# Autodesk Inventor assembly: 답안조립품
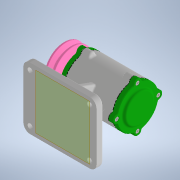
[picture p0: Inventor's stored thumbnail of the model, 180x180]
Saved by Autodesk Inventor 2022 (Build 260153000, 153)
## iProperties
Created: 2023-05
Part Number: 답안조립품
Document SubType Name: Assembly
Designer: Admin
Author: Admin
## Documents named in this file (12)
- C:\Users\Admin\Desktop\730508V1006\답안조립품.iam
- C:\Users\Admin\Desktop\730508V1006\본체.ipt
- C:\Users\Admin\Desktop\730508V1006\개스킷.ipt
- C:\Users\Admin\Desktop\730508V1006\앞커버.ipt
- C:\Users\Admin\Desktop\730508V1006\뒤커버.ipt
- C:\Users\Admin\Desktop\730508V1006\베어링 6204.ipt
- C:\Users\Admin\Desktop\730508V1006\오일 실.ipt
- C:\Users\Admin\Desktop\730508V1006\축.ipt
- C:\Users\Admin\Desktop\730508V1006\볼트 M4 x 12.ipt
- C:\Users\Admin\Desktop\730508V1006\키 4 x 4.ipt
- C:\Users\Admin\Desktop\730508V1006\V-벨트풀리.ipt
- C:\Users\Admin\Desktop\730508V1006\너트 M12 x 1.25.ipt
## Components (8 placed, 6 different names)
1. 개스킷:1
2. 개스킷:2
3. KS B 2023 6204 - 20 x 47 x 14:1
4. KS B 2023 6204 - 20 x 47 x 14:2
5. KS B 2804 D D - 20 32 8:1
6. KS B 1311 (I) 4 x 4 x 12:1
7. V-벨트풀리:1
8. KS B 1012 클래스 1 일반 - 미터 M12x1.25:1
